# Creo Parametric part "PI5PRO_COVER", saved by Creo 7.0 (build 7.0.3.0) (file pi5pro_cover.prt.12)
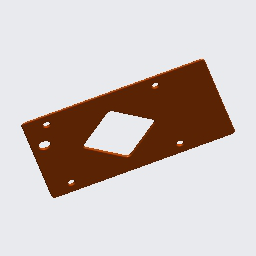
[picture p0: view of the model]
Units: millimeter Kilogram Sec (mmKs); MM, KILOGRAM, SECS

Created from: XX_SOLID_PART_MMKS_ABS.PRT

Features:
  1. coordinate system
  2. datum plane "RIGHT"
  3. datum plane "TOP"
  4. datum plane "FRONT"
  5. extrusion "Extrude 1"
  6. cut
  7. extruded cut "Extrude 3"
  8. extruded cut "Extrude 4"
  9. round "Round 1"
  10. round "Round 2"
  11. round "Round 3"
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
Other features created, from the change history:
  round "Round 1" (2 times)
  extruded cut "Extrude 4"
  extruded cut "Extrude 5" (2 times)
  extruded cut "Extrude 6"
  round "Round 2"
  round "Round 3"
  round "Round 4" (2 times)
  round "Round 5" (2 times)
  round "Round 6" (2 times)
  chamfer "Chamfer 1"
